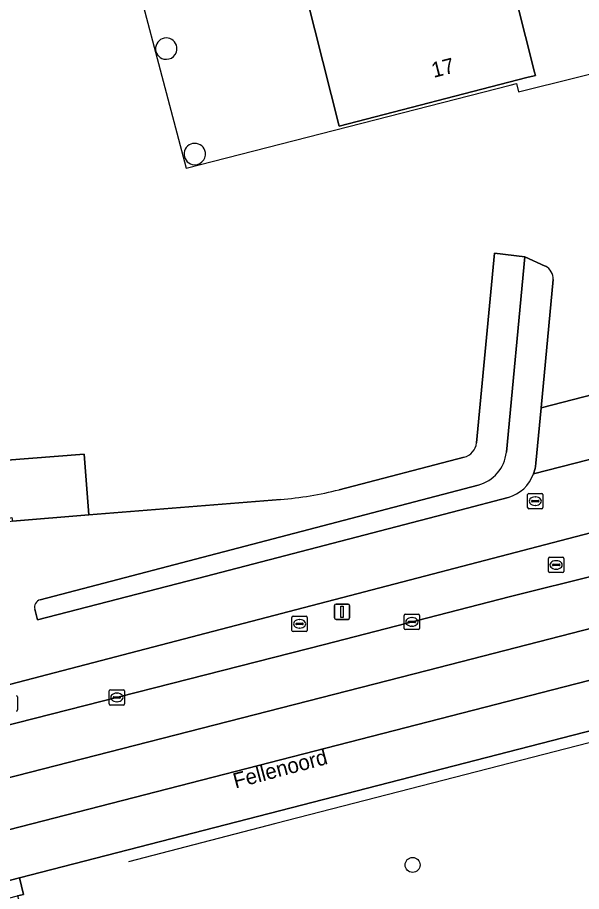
# Model space of a CAD drawing. Extents: x 160806 to 161707, y 383696 to 384148.
# Drawn here: x 161279.8 to 161316.7, y 383935.8 to 383992.9 of the extents above; entities that cross this region are included whole.
import ezdxf

# ---------------------------------------------------------------- set-up
doc = ezdxf.new("R2010")
doc.units = 0
for name, color, linetype in [('IMGEO_Berm_groen', 7, 'Continuous'), ('IMGEO_Boom', 7, 'Continuous'), ('IMGEO_Erf', 7, 'Continuous'), ('IMGEO_Groenvoorziening', 7, 'Continuous'), ('IMGEO_Hek', 7, 'Continuous'), ('IMGEO_Kolk', 7, 'Continuous'), ('IMGEO_Lichtmast', 7, 'Continuous'), ('IMGEO_Openbare_ruimte_label', 7, 'Continuous'), ('IMGEO_Pand', 7, 'Continuous'), ('IMGEO_Pand_nummerreeks', 7, 'Continuous'), ('IMGEO_Pand_overbouw', 7, 'Continuous'), ('IMGEO_Rijbaan_lokaal_gesloten', 7, 'Continuous'), ('IMGEO_Rioolput', 7, 'Continuous'), ('IMGEO_Voetpad_gesloten', 7, 'Continuous'), ('IMGEO_Voetpad_op_trap', 7, 'Continuous'), ('IMGEO_Voetpad_open', 7, 'Continuous')]:
    doc.layers.add(name, color=color, linetype=linetype)

msp = doc.modelspace()

# ---------------------------------------------------------------- linework, layer by layer
at = {"layer": 'IMGEO_Berm_groen'}
for points in [[(161465.14, 383986.182), (161455.902, 383982.36), (161453.055, 383981.256), (161450.194, 383980.461), (161341.031, 383952.394), (161279.919, 383936.647), (161280.177, 383935.571), (161279.794, 383935.48), (161279.911, 383935.042), (161282.439, 383924.956), (161282.559, 383924.49), (161282.934, 383924.586), (161283.186, 383923.58), (161283.395, 383923.636), (161338.43, 383938.073)], [(161318.287, 383959.498), (161275.829, 383948.409), (161276.409, 383945.95), (161299.869, 383951.918), (161311.972, 383955.039), (161317.913, 383956.519)]]:
    msp.add_lwpolyline(points, dxfattribs=at)
at = {"layer": 'IMGEO_Boom'}
msp.add_circle((161305.641, 383937.498), 0.489, dxfattribs=at)
at = {"layer": 'IMGEO_Erf'}
for points in [[(161255.944, 384052.5), (161269.44, 384000), (161277.147, 383970.021), (161277.255, 383970.048), (161278.831, 383963.961), (161284.147, 383964.369), (161284.463, 383960.399), (161296.995, 383961.414)], [(161314.852, 383975.798), (161314.058, 383967.401), (161320.231, 383968.987), (161321.418, 383981.73)], [(161309.829, 383965.107), (161311.003, 383977.521), (161312.991, 383977.283), (161314.329, 383976.67)], [(161300.843, 383962.049), (161309.022, 383964.174)]]:
    msp.add_lwpolyline(points, dxfattribs=at)
msp.add_lwpolyline([(161310.919, 384001.335), (161310.658, 384001.268), (161312.108, 383995.404), (161312.338, 383995.464), (161312.682, 383994.096), (161312.451, 383994.037), (161313.62, 383989.378), (161313.677, 383989.154), (161313.593, 383989.134), (161313.129, 383989.019), (161300.843, 383985.84), (161297.111, 384000.629), (161297.354, 384000.692), (161297.319, 384000.838), (161298.032, 384001.03), (161298.073, 384000.878), (161302.412, 384002.002), (161309.96, 384003.959), (161310.329, 384002.536), (161310.591, 384002.604)], close=True, dxfattribs=at)
for centre, radius, start, end in [((161289.525, 383990.908), 0.7, 7.8929, 256.8414), ((161289.526, 383990.908), 0.7, 256.8144, 7.9199), ((161291.388, 383984.01), 0.7, 7.8929, 256.8414), ((161291.389, 383984.01), 0.7, 256.8144, 7.9199), ((161313.922, 383975.833), 0.931, 357.8367, 64.0715), ((161308.738, 383965.236), 1.099, 285.0011, 353.2824), ((161295.251, 383983.958), 22.612, 274.4233, 284.3178)]:
    msp.add_arc(centre, radius, start, end, dxfattribs=at)
at = {"layer": 'IMGEO_Groenvoorziening'}
for points in [[(161314.329, 383976.67), (161312.991, 383977.283), (161311.782, 383964.497)], [(161313.55, 383963.082), (161313.66, 383963.436), (161313.686, 383963.573), (161313.715, 383963.777), (161314.058, 383967.401), (161314.852, 383975.798)], [(161309.928, 383962.353), (161281.272, 383954.848)], [(161308.729, 383960.719), (161311.907, 383961.542)], [(161280.914, 383954.227), (161281.104, 383953.53), (161291.557, 383956.232), (161308.729, 383960.719)]]:
    msp.add_lwpolyline(points, dxfattribs=at)
for centre, radius, start, end in [((161313.922, 383975.833), 0.931, 357.8367, 64.0715), ((161309.286, 383964.782), 2.513, 284.8118, 353.4857), ((161311.208, 383963.934), 2.492, 286.2888, 340.0044), ((161281.415, 383954.352), 0.517, 106.1159, 193.9581)]:
    msp.add_arc(centre, radius, start, end, dxfattribs=at)
at = {"layer": 'IMGEO_Hek'}
msp.add_lwpolyline([(161341.247, 383951.682), (161296.689, 383940.215), (161287.043, 383937.692)], dxfattribs=at)
at = {"layer": 'IMGEO_Kolk'}
for p, q in [((161305.096, 383952.97), (161305.096, 383953.822)), ((161305.171, 383953.896), (161306.023, 383953.896)), ((161305.584, 383953.676), (161305.609, 383953.676)), ((161306.097, 383953.822), (161306.097, 383952.97)), ((161305.355, 383953.39), (161305.355, 383953.402)), ((161305.793, 383953.353), (161305.395, 383953.353)), ((161305.398, 383953.439), (161305.796, 383953.439)), ((161305.607, 383953.116), (161305.582, 383953.116)), ((161305.839, 383953.402), (161305.839, 383953.39)), ((161306.023, 383952.896), (161305.171, 383952.896)), ((161285.868, 383948.956), (161286.72, 383948.956)), ((161285.793, 383948.03), (161285.793, 383948.882)), ((161286.052, 383948.45), (161286.052, 383948.462)), ((161286.49, 383948.413), (161286.092, 383948.413)), ((161286.095, 383948.499), (161286.493, 383948.499)), ((161286.281, 383948.736), (161286.306, 383948.736)), ((161286.536, 383948.462), (161286.536, 383948.45)), ((161286.794, 383948.882), (161286.794, 383948.03)), ((161286.72, 383947.956), (161285.868, 383947.956)), ((161286.304, 383948.176), (161286.279, 383948.176))]:
    msp.add_line(p, q, dxfattribs=at)
for points in [[(161305.096, 383952.97), (161305.096, 383953.822)], [(161305.171, 383953.896), (161306.023, 383953.896)], [(161306.097, 383953.822), (161306.097, 383952.97)], [(161306.023, 383952.896), (161305.171, 383952.896)], [(161285.868, 383948.956), (161286.72, 383948.956)], [(161285.793, 383948.03), (161285.793, 383948.882)], [(161286.794, 383948.882), (161286.794, 383948.03)], [(161286.72, 383947.956), (161285.868, 383947.956)]]:
    msp.add_lwpolyline(points, dxfattribs=at)
for centre, radius, start, end in [((161305.173, 383953.82), 0.0765, 91.552, 178.448), ((161305.173, 383953.82), 0.0765, 91.552, 178.448), ((161306.021, 383953.82), 0.0765, 1.552, 88.448), ((161306.021, 383953.82), 0.0765, 1.552, 88.448), ((161305.173, 383952.972), 0.0765, 181.552, 268.448), ((161305.173, 383952.972), 0.0765, 181.552, 268.448), ((161305.395, 383953.399), 0.0403, 85.8775, 175.7526), ((161305.392, 383953.389), 0.0366, 178.938, 274.7102), ((161305.796, 383953.396), 0.043, 264.8664, 352.4533), ((161305.8, 383953.401), 0.0386, 1.7309, 96.639), ((161306.021, 383952.972), 0.0765, 271.552, 358.448), ((161306.021, 383952.972), 0.0765, 271.552, 358.448), ((161285.87, 383948.88), 0.0765, 91.552, 178.448), ((161285.87, 383948.88), 0.0765, 91.552, 178.448), ((161286.718, 383948.88), 0.0765, 1.552, 88.448), ((161286.718, 383948.88), 0.0765, 1.552, 88.448), ((161286.092, 383948.459), 0.0403, 85.8775, 175.7526), ((161286.089, 383948.449), 0.0366, 178.938, 274.7102), ((161286.493, 383948.456), 0.043, 264.8664, 352.4533), ((161286.497, 383948.461), 0.0386, 1.7309, 96.639), ((161285.87, 383948.032), 0.0765, 181.552, 268.448), ((161285.87, 383948.032), 0.0765, 181.552, 268.448), ((161286.718, 383948.032), 0.0765, 271.552, 358.448), ((161286.718, 383948.032), 0.0765, 271.552, 358.448)]:
    msp.add_arc(centre, radius, start, end, dxfattribs=at)
for centre, major_axis, ratio, start_param, end_param in [((161305.583, 383953.396), (-0.387, 0.002), 0.722429, 4.712389, 7.853982), ((161305.608, 383953.396), (-0.39, 0.002), 0.717154, 1.570796, 4.712389), ((161286.28, 383948.456), (-0.387, 0.002), 0.722429, 4.712389, 7.853982), ((161286.305, 383948.456), (-0.39, 0.002), 0.717154, 1.570796, 4.712389)]:
    msp.add_ellipse(centre, major_axis=major_axis, ratio=ratio, start_param=start_param, end_param=end_param, dxfattribs=at)
at = {"layer": 'IMGEO_Lichtmast'}
for p, q in [((161300.532, 383953.661), (161300.532, 383954.461)), ((161300.532, 383954.461), (161300.532, 383953.661)), ((161300.632, 383954.561), (161301.422, 383954.561)), ((161301.422, 383954.561), (161300.632, 383954.561)), ((161301.522, 383954.461), (161301.522, 383953.661)), ((161301.522, 383953.661), (161301.522, 383954.461)), ((161301.422, 383953.561), (161300.632, 383953.561)), ((161300.632, 383953.561), (161301.422, 383953.561))]:
    msp.add_line(p, q, dxfattribs=at)
msp.add_lwpolyline([(161300.952, 383954.436), (161301.102, 383954.436), (161301.102, 383953.686), (161300.952, 383953.686), (161300.952, 383954.436)], dxfattribs=at)
for centre, start, end in [((161300.632, 383954.461), 90, 180), ((161300.632, 383954.461), 90, 180), ((161301.422, 383954.461), 0, 90), ((161301.422, 383954.461), 360, 90), ((161300.632, 383953.661), 180, 270), ((161300.632, 383953.661), 180, 270), ((161301.422, 383953.661), 270, 0), ((161301.422, 383953.661), 270, 0)]:
    msp.add_arc(centre, 0.1, start, end, dxfattribs=at)
at = {"layer": 'IMGEO_Pand'}
msp.add_lwpolyline([(161310.658, 384001.268), (161310.919, 384001.335), (161310.591, 384002.604), (161310.329, 384002.536), (161309.96, 384003.959), (161302.412, 384002.002), (161298.073, 384000.878), (161298.032, 384001.03), (161297.319, 384000.838), (161297.354, 384000.692), (161297.111, 384000.629), (161300.843, 383985.84), (161313.129, 383989.019), (161313.593, 383989.134), (161313.677, 383989.154), (161313.62, 383989.378), (161312.451, 383994.037), (161312.682, 383994.096), (161312.338, 383995.464), (161312.108, 383995.404)], close=True, dxfattribs=at)
for centre, start, end in [((161289.525, 383990.908), 7.8929, 256.8414), ((161289.526, 383990.908), 256.8144, 7.9199), ((161291.388, 383984.01), 7.8929, 256.8414), ((161291.389, 383984.01), 256.8144, 7.9199)]:
    msp.add_arc(centre, 0.7, start, end, dxfattribs=at)
at = {"layer": 'IMGEO_Pand_overbouw'}
msp.add_lwpolyline([(161286.226, 384000.503), (161290.822, 383983.081), (161312.031, 383988.52), (161312.432, 383988.623), (161312.567, 383988.079), (161331.698, 383992.825), (161336.907, 383994.117)], dxfattribs=at)
at = {"layer": 'IMGEO_Rijbaan_lokaal_gesloten'}
for points in [[(161465.227, 383987.648), (161464.472, 383990.836), (161453.394, 383987.997), (161409.072, 383976.597), (161362.907, 383964.706), (161339.296, 383958.642), (161306.607, 383950.212), (161270.989, 383941.101), (161271.807, 383937.9), (161315.559, 383949.156), (161335.194, 383954.191), (161340.223, 383955.497), (161347.001, 383957.235), (161378.316, 383965.298), (161419.642, 383975.931), (161451.011, 383984.005)], [(161450.194, 383980.461), (161453.055, 383981.256), (161455.902, 383982.36), (161465.14, 383986.182), (161465.535, 383986.348), (161465.227, 383987.648), (161451.011, 383984.005), (161419.642, 383975.931), (161378.316, 383965.298), (161347.001, 383957.235), (161340.223, 383955.497), (161335.194, 383954.191), (161315.559, 383949.156), (161271.807, 383937.9), (161272.608, 383934.763), (161279.919, 383936.647), (161341.031, 383952.394)]]:
    msp.add_lwpolyline(points, close=True, dxfattribs=at)
msp.add_lwpolyline([(161317.913, 383956.519), (161311.972, 383955.039), (161299.869, 383951.918), (161276.409, 383945.95), (161272.827, 383945.039), (161270.159, 383944.353), (161270.989, 383941.101), (161306.607, 383950.212), (161339.296, 383958.642)], dxfattribs=at)
at = {"layer": 'IMGEO_Rioolput'}
for p, q in [((161313.172, 383960.873), (161313.172, 383961.725)), ((161313.247, 383961.799), (161314.099, 383961.799)), ((161313.66, 383961.579), (161313.685, 383961.579)), ((161314.173, 383961.725), (161314.173, 383960.873)), ((161313.431, 383961.293), (161313.431, 383961.305)), ((161313.869, 383961.256), (161313.471, 383961.256)), ((161313.474, 383961.342), (161313.872, 383961.342)), ((161313.683, 383961.019), (161313.658, 383961.019)), ((161313.915, 383961.305), (161313.915, 383961.293)), ((161314.099, 383960.799), (161313.247, 383960.799)), ((161314.534, 383956.699), (161314.534, 383957.551)), ((161314.609, 383957.625), (161315.461, 383957.625)), ((161315.535, 383957.551), (161315.535, 383956.699)), ((161314.793, 383957.119), (161314.793, 383957.131)), ((161315.231, 383957.082), (161314.833, 383957.082)), ((161314.836, 383957.168), (161315.234, 383957.168)), ((161315.022, 383957.405), (161315.047, 383957.405)), ((161315.277, 383957.131), (161315.277, 383957.119)), ((161315.461, 383956.625), (161314.609, 383956.625)), ((161315.045, 383956.845), (161315.02, 383956.845)), ((161297.749, 383952.844), (161297.749, 383953.696)), ((161297.824, 383953.77), (161298.676, 383953.77)), ((161298.237, 383953.55), (161298.262, 383953.55)), ((161298.75, 383953.696), (161298.75, 383952.844)), ((161298.008, 383953.264), (161298.008, 383953.276)), ((161298.446, 383953.227), (161298.048, 383953.227)), ((161298.051, 383953.313), (161298.449, 383953.313)), ((161298.26, 383952.99), (161298.235, 383952.99)), ((161298.492, 383953.276), (161298.492, 383953.264)), ((161298.676, 383952.77), (161297.824, 383952.77)), ((161279.787, 383948.493), (161279.787, 383947.641))]:
    msp.add_line(p, q, dxfattribs=at)
for points in [[(161313.172, 383960.873), (161313.172, 383961.725)], [(161313.247, 383961.799), (161314.099, 383961.799)], [(161314.173, 383961.725), (161314.173, 383960.873)], [(161314.099, 383960.799), (161313.247, 383960.799)], [(161314.534, 383956.699), (161314.534, 383957.551)], [(161314.609, 383957.625), (161315.461, 383957.625)], [(161315.535, 383957.551), (161315.535, 383956.699)], [(161315.461, 383956.625), (161314.609, 383956.625)], [(161297.749, 383952.844), (161297.749, 383953.696)], [(161297.824, 383953.77), (161298.676, 383953.77)], [(161298.75, 383953.696), (161298.75, 383952.844)], [(161298.676, 383952.77), (161297.824, 383952.77)], [(161279.787, 383948.493), (161279.787, 383947.641)]]:
    msp.add_lwpolyline(points, dxfattribs=at)
for centre, radius, start, end in [((161313.249, 383961.723), 0.0765, 91.552, 178.448), ((161313.249, 383961.723), 0.0765, 91.552, 178.448), ((161314.097, 383961.723), 0.0765, 1.552, 88.448), ((161314.097, 383961.723), 0.0765, 1.552, 88.448), ((161313.471, 383961.302), 0.0403, 85.8775, 175.7526), ((161313.468, 383961.292), 0.0366, 178.938, 274.7102), ((161313.872, 383961.299), 0.043, 264.8664, 352.4533), ((161313.876, 383961.304), 0.0386, 1.7309, 96.639), ((161313.249, 383960.875), 0.0765, 181.552, 268.448), ((161313.249, 383960.875), 0.0765, 181.552, 268.448), ((161314.097, 383960.875), 0.0765, 271.552, 358.448), ((161314.097, 383960.875), 0.0765, 271.552, 358.448), ((161314.611, 383957.549), 0.0765, 91.552, 178.448), ((161314.611, 383957.549), 0.0765, 91.552, 178.448), ((161315.459, 383957.549), 0.0765, 1.552, 88.448), ((161315.459, 383957.549), 0.0765, 1.552, 88.448), ((161314.833, 383957.128), 0.0403, 85.8775, 175.7526), ((161314.83, 383957.118), 0.0366, 178.938, 274.7102), ((161315.234, 383957.125), 0.043, 264.8664, 352.4533), ((161315.238, 383957.13), 0.0386, 1.7309, 96.639), ((161314.611, 383956.701), 0.0765, 181.552, 268.448), ((161314.611, 383956.701), 0.0765, 181.552, 268.448), ((161315.459, 383956.701), 0.0765, 271.552, 358.448), ((161315.459, 383956.701), 0.0765, 271.552, 358.448), ((161297.826, 383953.694), 0.0765, 91.552, 178.448), ((161297.826, 383953.694), 0.0765, 91.552, 178.448), ((161298.674, 383953.694), 0.0765, 1.552, 88.448), ((161298.674, 383953.694), 0.0765, 1.552, 88.448), ((161298.048, 383953.273), 0.0403, 85.8775, 175.7526), ((161298.045, 383953.263), 0.0366, 178.938, 274.7102), ((161298.449, 383953.27), 0.043, 264.8664, 352.4533), ((161298.453, 383953.275), 0.0386, 1.7309, 96.639), ((161297.826, 383952.846), 0.0765, 181.552, 268.448), ((161297.826, 383952.846), 0.0765, 181.552, 268.448), ((161298.674, 383952.846), 0.0765, 271.552, 358.448), ((161298.674, 383952.846), 0.0765, 271.552, 358.448), ((161279.711, 383948.491), 0.0765, 1.552, 88.448), ((161279.711, 383948.491), 0.0765, 1.552, 88.448), ((161279.711, 383947.643), 0.0765, 271.552, 358.448), ((161279.711, 383947.643), 0.0765, 271.552, 358.448)]:
    msp.add_arc(centre, radius, start, end, dxfattribs=at)
for centre, major_axis, ratio, start_param, end_param in [((161313.659, 383961.299), (-0.387, 0.002), 0.722429, 4.712389, 7.853982), ((161313.684, 383961.299), (-0.39, 0.002), 0.717154, 1.570796, 4.712389), ((161315.021, 383957.125), (-0.387, 0.002), 0.722429, 4.712389, 7.853982), ((161315.046, 383957.125), (-0.39, 0.002), 0.717154, 1.570796, 4.712389), ((161298.236, 383953.27), (-0.387, 0.002), 0.722429, 4.712389, 7.853982), ((161298.261, 383953.27), (-0.39, 0.002), 0.717154, 1.570796, 4.712389)]:
    msp.add_ellipse(centre, major_axis=major_axis, ratio=ratio, start_param=start_param, end_param=end_param, dxfattribs=at)
at = {"layer": 'IMGEO_Voetpad_gesloten'}
msp.add_lwpolyline([(161284.147, 383964.369), (161278.831, 383963.961), (161267.055, 383960.972), (161268.056, 383957.312), (161268.937, 383957.545), (161279.41, 383960.225), (161279.47, 383959.995), (161284.463, 383960.399)], close=True, dxfattribs=at)
at = {"layer": 'IMGEO_Voetpad_op_trap'}
msp.add_lwpolyline([(161319.913, 383965.574), (161320.231, 383968.987), (161314.058, 383967.401), (161313.715, 383963.777), (161313.686, 383963.573), (161313.66, 383963.436), (161313.55, 383963.082), (161319.775, 383964.679), (161319.793, 383964.851), (161319.845, 383964.864)], close=True, dxfattribs=at)
at = {"layer": 'IMGEO_Voetpad_open'}
for points in [[(161296.995, 383961.414), (161284.463, 383960.399), (161279.47, 383959.995), (161277.942, 383959.608), (161276.704, 383959.287), (161276.807, 383958.971), (161275.086, 383958.531), (161275.946, 383955.106), (161277.665, 383955.564), (161277.792, 383955.075), (161274.456, 383954.218), (161275.3, 383950.645), (161275.829, 383948.409), (161318.287, 383959.498), (161370.444, 383973.147), (161369.289, 383977.37), (161414.805, 383989.287)], [(161311.782, 383964.497), (161312.991, 383977.283), (161311.003, 383977.521), (161309.829, 383965.107)], [(161319.775, 383964.679), (161313.55, 383963.082)], [(161309.022, 383964.174), (161300.843, 383962.049)], [(161281.272, 383954.848), (161309.928, 383962.353)], [(161311.907, 383961.542), (161308.729, 383960.719), (161291.557, 383956.232), (161281.104, 383953.53), (161280.914, 383954.227)]]:
    msp.add_lwpolyline(points, dxfattribs=at)
msp.add_lwpolyline([(161279.794, 383935.48), (161280.177, 383935.571), (161279.919, 383936.647), (161272.608, 383934.763), (161272.881, 383933.693)], close=True, dxfattribs=at)
for centre, radius, start, end in [((161308.738, 383965.236), 1.099, 285.0011, 353.2824), ((161309.286, 383964.782), 2.513, 284.8118, 353.4857), ((161311.208, 383963.934), 2.492, 286.2888, 340.0044), ((161295.251, 383983.958), 22.612, 274.4233, 284.3178), ((161281.415, 383954.352), 0.517, 106.1159, 193.9581)]:
    msp.add_arc(centre, radius, start, end, dxfattribs=at)

# ---------------------------------------------------------------- texts
at = {"layer": 'IMGEO_Openbare_ruimte_label'}
msp.add_text('Fellenoord', height=1, rotation=14.9536, dxfattribs=at).set_placement((161294.05, 383942.49))
at = {"layer": 'IMGEO_Pand_nummerreeks'}
msp.add_text('17', height=1, rotation=14.3068, dxfattribs=at).set_placement((161307.02, 383988.991))

doc.saveas('drawing.dxf')
